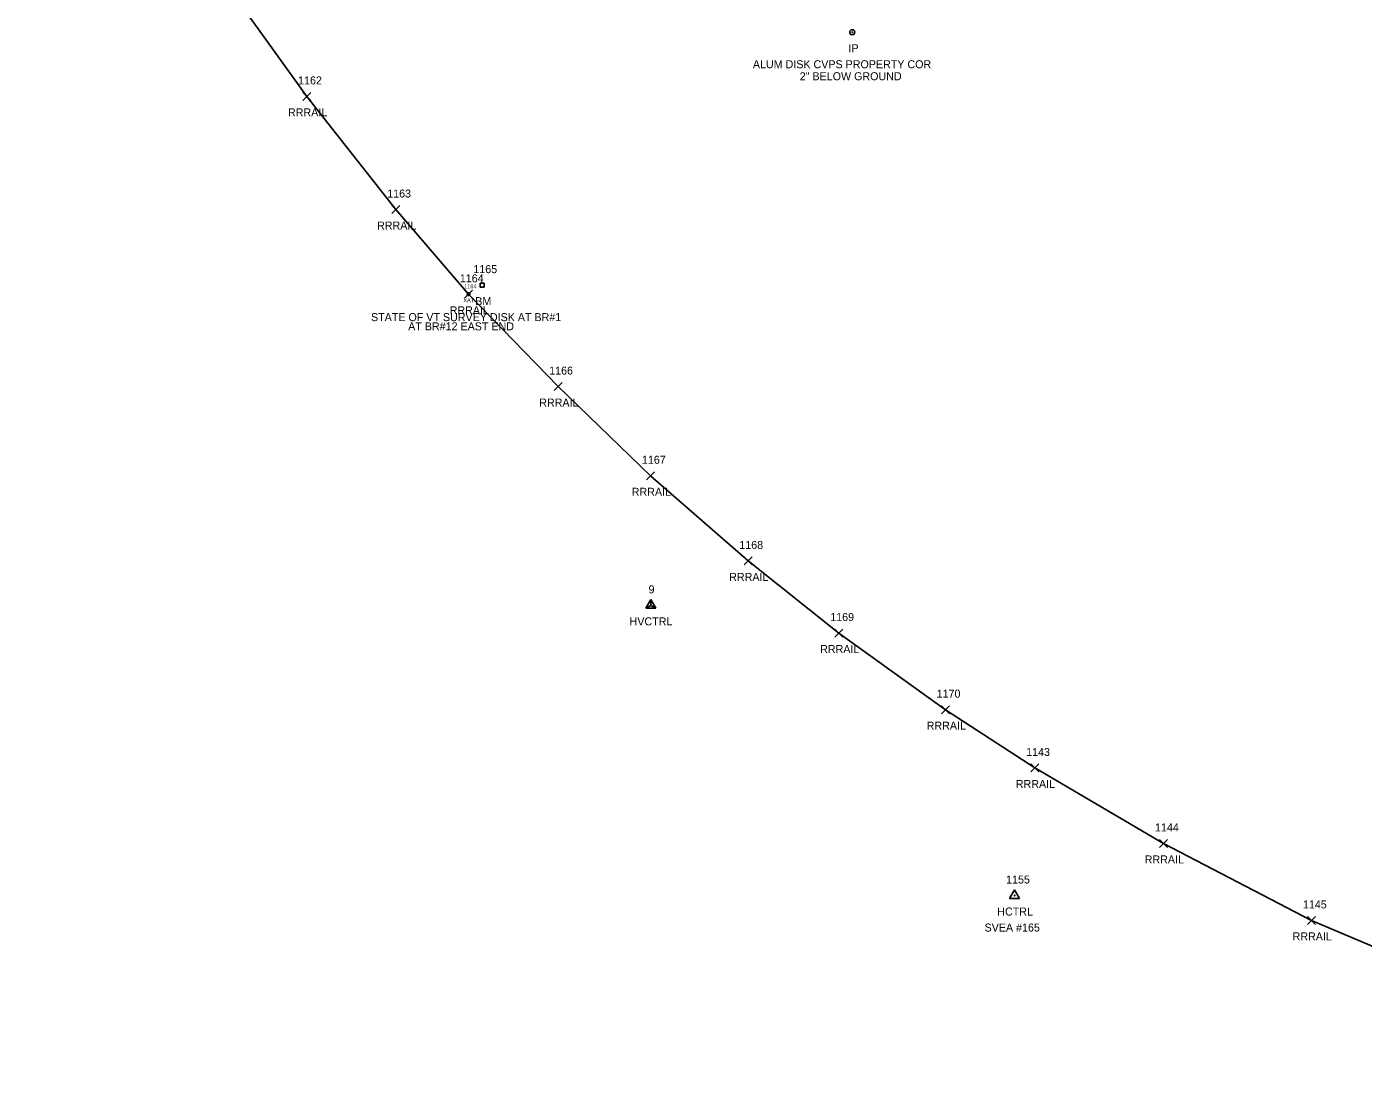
# Model space of a CAD drawing. Extents: x 1764889 to 1767296, y 695936 to 698960.
# Drawn here: x 1764952.4 to 1765286.6, y 695956.9 to 696222.3 of the extents above; entities that cross this region are included whole.
import ezdxf

# ---------------------------------------------------------------- set-up
doc = ezdxf.new("R2010")
doc.units = 0
for name, color, linetype in [('B_A', 7, 'Continuous'), ('B_I', 7, 'Continuous'), ('B_TIC', 7, 'Continuous'), ('C_A', 7, 'Continuous'), ('C_C', 7, 'Continuous'), ('C_I', 7, 'Continuous'), ('CPBM', 7, 'Continuous'), ('CPH', 7, 'Continuous'), ('CPSM', 7, 'Continuous'), ('M_A', 7, 'Continuous'), ('M_C', 7, 'Continuous'), ('MPIR', 7, 'Continuous'), ('R_A', 7, 'Continuous'), ('R_C', 7, 'Continuous'), ('R_I', 7, 'Continuous'), ('R_TIC', 7, 'Continuous'), ('RR', 7, 'Continuous')]:
    doc.layers.add(name, color=color, linetype=linetype)

msp = doc.modelspace()

# ---------------------------------------------------------------- linework, layer by layer
at = {"layer": 'B_TIC'}
msp.add_line((1765062.88, 696155.39), (1765062.95, 696155.39), dxfattribs=at)
for points in [[(1765062.37, 696155.39), (1765063.37, 696155.39)], [(1765062.87, 696154.89), (1765062.87, 696155.89)]]:
    msp.add_lwpolyline(points, dxfattribs=at)
at = {"layer": 'CPBM'}
for p, q in [((1765065.75, 696157.18), (1765065.75, 696158.18)), ((1765065.75, 696158.18), (1765066.75, 696158.18)), ((1765065.75, 696157.18), (1765065.75, 696158.18)), ((1765065.75, 696158.18), (1765066.75, 696158.18)), ((1765065.75, 696157.18), (1765065.75, 696158.18)), ((1765065.75, 696158.18), (1765066.75, 696158.18)), ((1765066.25, 696157.68), (1765066.25, 696157.68)), ((1765066.25, 696157.68), (1765066.25, 696157.68)), ((1765066.25, 696157.68), (1765066.25, 696157.68)), ((1765066.25, 696157.68), (1765066.25, 696157.68)), ((1765066.25, 696157.68), (1765066.25, 696157.68)), ((1765066.25, 696157.68), (1765066.25, 696157.68)), ((1765066.75, 696158.18), (1765066.75, 696157.18)), ((1765066.75, 696158.18), (1765066.75, 696157.18)), ((1765066.75, 696158.18), (1765066.75, 696157.18)), ((1765066.75, 696157.18), (1765065.75, 696157.18)), ((1765066.75, 696157.18), (1765065.75, 696157.18)), ((1765066.75, 696157.18), (1765065.75, 696157.18))]:
    msp.add_line(p, q, dxfattribs=at)
at = {"layer": 'CPH'}
for p, q in [((1765198.14, 696004.38), (1765199.39, 696006.55)), ((1765198.14, 696004.38), (1765199.39, 696006.55)), ((1765198.14, 696004.38), (1765200.64, 696004.38)), ((1765198.14, 696004.38), (1765200.64, 696004.38)), ((1765200.64, 696004.38), (1765199.39, 696006.55)), ((1765200.64, 696004.38), (1765199.39, 696006.55)), ((1765199.39, 696005.1), (1765199.39, 696005.1)), ((1765199.39, 696005.1), (1765199.39, 696005.1))]:
    msp.add_line(p, q, dxfattribs=at)
msp.add_circle((1765199.39, 696005.1), 0.0833, dxfattribs=at)
msp.add_circle((1765199.39, 696005.1), 0.0833, dxfattribs=at)
at = {"layer": 'CPSM'}
for p, q in [((1765107.2, 696076.91), (1765108.45, 696079.07)), ((1765107.2, 696076.91), (1765108.45, 696079.07)), ((1765107.2, 696076.91), (1765108.45, 696077.63)), ((1765107.2, 696076.91), (1765108.45, 696077.63)), ((1765109.7, 696076.91), (1765108.45, 696079.07)), ((1765108.45, 696077.63), (1765108.45, 696079.07)), ((1765109.7, 696076.91), (1765108.45, 696079.07)), ((1765108.45, 696077.63), (1765108.45, 696079.07)), ((1765108.45, 696077.63), (1765108.45, 696077.63)), ((1765108.45, 696077.63), (1765109.7, 696076.91)), ((1765108.45, 696077.63), (1765108.45, 696077.63)), ((1765108.45, 696077.63), (1765109.7, 696076.91)), ((1765107.2, 696076.91), (1765109.7, 696076.91)), ((1765107.2, 696076.91), (1765109.7, 696076.91))]:
    msp.add_line(p, q, dxfattribs=at)
at = {"layer": 'MPIR'}
for radius in [0.625, 0.0833]:
    msp.add_circle((1765158.8, 696220.9), radius, dxfattribs=at)
at = {"layer": 'R_TIC'}
for points in [[(1765021.45, 696203.87), (1765023.45, 696205.87)], [(1765023.45, 696203.87), (1765021.45, 696205.87)], [(1765043.73, 696175.58), (1765045.73, 696177.58)], [(1765045.73, 696175.58), (1765043.73, 696177.58)], [(1765061.87, 696154.39), (1765063.87, 696156.39)], [(1765063.87, 696154.39), (1765061.87, 696156.39)], [(1765084.26, 696131.32), (1765086.26, 696133.32)], [(1765086.26, 696131.32), (1765084.26, 696133.32)], [(1765107.4, 696109.02), (1765109.4, 696111.02)], [(1765109.4, 696109.02), (1765107.4, 696111.02)], [(1765131.75, 696087.74), (1765133.75, 696089.74)], [(1765133.75, 696087.74), (1765131.75, 696089.74)], [(1765154.49, 696069.71), (1765156.49, 696071.71)], [(1765156.49, 696069.71), (1765154.49, 696071.71)], [(1765181.12, 696050.56), (1765183.12, 696052.56)], [(1765183.12, 696050.56), (1765181.12, 696052.56)], [(1765181.12, 696050.56), (1765183.12, 696052.56)], [(1765183.12, 696050.56), (1765181.12, 696052.56)], [(1765203.41, 696035.98), (1765205.41, 696037.98)], [(1765205.41, 696035.98), (1765203.41, 696037.98)], [(1765203.41, 696035.98), (1765205.41, 696037.98)], [(1765205.41, 696035.98), (1765203.41, 696037.98)], [(1765235.61, 696017.12), (1765237.61, 696019.12)], [(1765237.61, 696017.12), (1765235.61, 696019.12)], [(1765272.6, 695997.88), (1765274.6, 695999.88)], [(1765274.6, 695997.88), (1765272.6, 695999.88)]]:
    msp.add_lwpolyline(points, dxfattribs=at)
at = {"layer": 'RR'}
for points in [[(1764952.43, 696322.53), (1764965.18, 696296.46), (1764973.9, 696280.22), (1764988.82, 696254.65), (1765005.8, 696228.03), (1765022.45, 696204.87), (1765044.73, 696176.58), (1765062.87, 696155.39), (1765085.26, 696132.32), (1765108.4, 696110.02), (1765132.75, 696088.74), (1765155.49, 696070.71), (1765182.12, 696051.56)], [(1765204.41, 696036.98), (1765182.12, 696051.56)], [(1765204.41, 696036.98), (1765236.61, 696018.12), (1765273.6, 695998.88), (1765307.12, 695984.71), (1765335.82, 695975.26), (1765368.12, 695967.16), (1765396.2, 695962.44), (1765422.61, 695959.21), (1765444.52, 695957.45), (1765468.68, 695956.92)]]:
    msp.add_lwpolyline(points, dxfattribs=at)

# ---------------------------------------------------------------- texts
at = {"layer": 'B_A'}
msp.add_text('XAT', height=1, dxfattribs=at).set_placement((1765061.58, 696153.39))
at = {"layer": 'B_I'}
msp.add_text('1164', height=1, dxfattribs=at).set_placement((1765061.79, 696156.89))
at = {"layer": 'C_A'}
for s, p in [('BM', (1765064.56, 696152.68)), ('BM', (1765064.56, 696152.68)), ('BM', (1765064.56, 696152.68)), ('HVCTRL', (1765103.14, 696072.63)), ('HVCTRL', (1765103.14, 696072.63)), ('HCTRL', (1765195.06, 696000.1)), ('HCTRL', (1765195.06, 696000.1))]:
    msp.add_text(s, height=2, dxfattribs=at).set_placement(p)
at = {"layer": 'C_C'}
for s, p in [('STATE OF VT SURVEY DISK AT BR#1', (1765038.5, 696148.68)), ('STATE OF VT SURVEY DISK AT BR#1', (1765038.5, 696148.68)), ('STATE OF VT SURVEY DISK AT BR#1', (1765038.5, 696148.68)), ('SVEA #165', (1765191.88, 695996.1)), ('SVEA #165', (1765191.88, 695996.1))]:
    msp.add_text(s, height=2, dxfattribs=at).set_placement(p)
at = {"layer": 'C_I'}
for s, p in [('1165', (1765064.08, 696160.68)), ('1165', (1765064.08, 696160.68)), ('1165', (1765064.08, 696160.68)), ('9', (1765107.88, 696080.63)), ('9', (1765107.88, 696080.63)), ('1155', (1765197.27, 696008.1)), ('1155', (1765197.27, 696008.1))]:
    msp.add_text(s, height=2, dxfattribs=at).set_placement(p)
at = {"layer": 'M_A'}
msp.add_text('IP', height=2, dxfattribs=at).set_placement((1765157.85, 696215.9))
at = {"layer": 'M_C'}
for s, p in [('ALUM DISK CVPS PROPERTY COR', (1765133.96, 696211.9)), ('2" BELOW GROUND', (1765145.68, 696208.9))]:
    msp.add_text(s, height=2, dxfattribs=at).set_placement(p)
at = {"layer": 'R_A'}
for p in [(1765017.75, 696199.87), (1765040.02, 696171.58), (1765058.16, 696150.39), (1765080.56, 696127.32), (1765103.69, 696105.02), (1765128.04, 696083.74), (1765150.78, 696065.71), (1765177.41, 696046.56), (1765177.41, 696046.56), (1765199.7, 696031.98), (1765199.7, 696031.98), (1765231.91, 696013.12), (1765268.89, 695993.88)]:
    msp.add_text('RRRAIL', height=2, dxfattribs=at).set_placement(p)
at = {"layer": 'R_C'}
msp.add_text('AT BR#12 EAST END', height=2, dxfattribs=at).set_placement((1765047.79, 696146.39))
at = {"layer": 'R_I'}
for s, p in [('1162', (1765020.28, 696207.87)), ('1163', (1765042.55, 696179.58)), ('1164', (1765060.7, 696158.39)), ('1166', (1765083.04, 696135.32)), ('1167', (1765106.23, 696113.02)), ('1168', (1765130.57, 696091.74)), ('1169', (1765153.3, 696073.71)), ('1170', (1765179.9, 696054.56)), ('1170', (1765179.9, 696054.56)), ('1143', (1765202.28, 696039.98)), ('1143', (1765202.28, 696039.98)), ('1144', (1765234.49, 696021.12)), ('1145', (1765271.47, 696001.88))]:
    msp.add_text(s, height=2, dxfattribs=at).set_placement(p)

doc.saveas('drawing.dxf')
